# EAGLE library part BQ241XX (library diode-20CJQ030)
Texas Instruments bqSwitcher BQ241xx synchronous switchmode, LI-ION and LI-POL charge management IC with integrated powerfets DESCRIPTION: The bqSWITCHER series are highly integrated Li-ion and Li-polymer switch-mode charge management devices targeted at a wide range of portable applications. The bqSWITCHER series offers integrated synchronous PWM controller and power FETs, high-accuracy current and voltage regulation, charge preconditioning, charge status, and charge termination, in a small, thermally enhanced QFN package. The system-controlled version provides additional inputs for full charge management under system control. The bqSWITCHER charges the battery in three phases: conditioning, constant current, and constant voltage. Charge is terminated based on user-selectable minimum current level. A programmable charge timer provides a safety backup for charge termination. The bqSWITCHER automatically re-starts the charge cycle if the battery voltage falls below an internal threshold. The bqSWITCHER automatically enters sleep mode when VCC supply is removed. FEATURES: Ideal For High-Efficient Charger Designs For Single-, Two- or Three-Cell Li-Ion and Li-Pol Battery Packs Integrated Synchronous Fixed-Frequency PWM Controller Operating at 1.1 MHz with 0 to 100% Duty Cycle Integrated PowerFETs For Up To 2-A Charge Rate High-Accuracy Voltage and Current Regulation Available In Both Stand-Alone (Built-In Charge Management and Control) and System-Controlled (Under System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
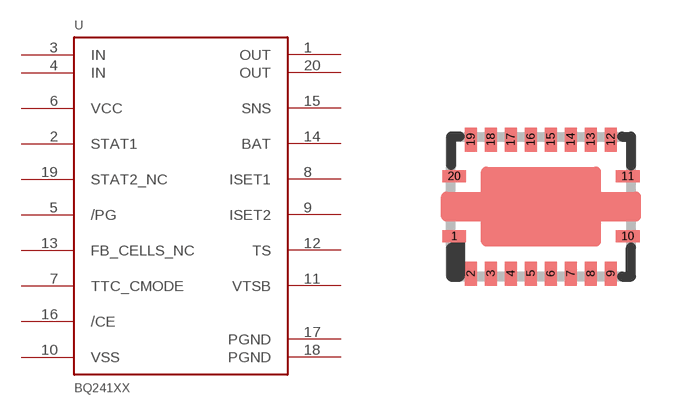
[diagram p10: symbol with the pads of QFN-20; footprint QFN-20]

Designator prefix U

## BQ241XX  [QFN-20]
1  OUT  out
2  STAT1  out
3  IN  in
4  IN  in
5  /PG  out
6  VCC  pwr
7  TTC_CMODE  in
8  ISET1
9  ISET2
10  VSS  pwr
11  VTSB  out
12  TS  in
13  FB_CELLS_NC  in
14  BAT  in
15  SNS  in
16  /CE  in
17  PGND  pwr
18  PGND  pwr
19  STAT2_NC  out
20  OUT  pas

## Footprint QFN-20 (pad centres in mm)
TI bqSwitcher battery chargers BQ241xx (central pad is ground)
smd 0.6 x 0.3: 1 -2.17,-0.745; 10 2.17,-0.745; 11 2.17,0.755; 20 -2.17,0.755
smd 0.3 x 0.6: 2 -1.75,-1.675; 3 -1.25,-1.675; 4 -0.75,-1.675; 5 -0.25,-1.675; 6 0.25,-1.675; 7 0.75,-1.675; 8 1.25,-1.675; 9 1.75,-1.675; 12 1.75,1.675; 13 1.25,1.675; 14 0.75,1.675; 15 0.25,1.675; 16 -0.25,1.675; 17 -0.75,1.675; 18 -1.25,1.675; 19 -1.75,1.675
